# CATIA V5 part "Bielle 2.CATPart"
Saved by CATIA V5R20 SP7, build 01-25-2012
Part number: Bielle 2
Bounding box of the stored display mesh (mm): x -220 to 220, y 38.501 to 109.817, z 32.185 to 88.096
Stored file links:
  F:\Travaux\Modélisations\CFAO_2011\MMS\MMS_GR2\AA_OK\tquattrone\Catia\Bielle 2.CATPart
  C:\Users\Tom\Documents\Cours 2A\CFAO\Projet thinkmotion\Aileron_citroen.CATProduct
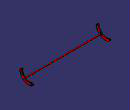
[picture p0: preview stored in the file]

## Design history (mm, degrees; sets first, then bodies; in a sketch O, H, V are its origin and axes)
Parameters
  Diametre_trou_bielle2 = 6 mm
  Epaisseur_bielle_2 = 5 mm
  `Distance_point/bielle2` = 5 mm
Set1
  Plane1 "Plan_bielle2/3": linked copy from another document
  Point1 "Point_bielle_21": linked copy from another document
  Point2 "Point_bielle_22": linked copy from another document
  Plane2 "Plan_sym": linked copy from another document
  Point3 "Point_bielle_11": linked copy from another document
  Plane3 "Plan_bielle1": linked copy from another document
Body1 (main body)
  Sketch1 on Plane1, origin (210, 0, 0), H (0, 1, 0), V (0, 0, 1)
    spline S1 through (49.3154, 81.8022) (52.0902, 68.1218) (61.1552, 54.5165) (77.3137, 44.9627) (95.4529, 44.3107) (100.0076, 45.2495) (108.0919, 44.8193) (109.4078, 38.541) (106.1441, 35.3786) (97.1685, 32.9047) (75.6566, 33.3551) (62.5105, 38.8193) (49.5126, 50.4629) (42.2393, 62.9606) (38.5014, 80.2129) (41.631, 87.7151) (44.3598, 88.0962) (46.5908, 87.3936)
    reference projected point E1 (44, 83) from Point2
    reference projected point E2 (104, 41) from Point1
    distance E1 S1 = 5 {= `Distance_point/bielle2`}
    distance E2 S1 = 5 {= `Distance_point/bielle2`}
  Pad1: profile Sketch1, direction (1, 0, 0), length 5 {= Epaisseur_bielle_2}
  Sketch2 on start face of Pad1, origin (210, 0, 0), H (0, -1, 0), V (0, 0, 1)
    circle A1 centre (-59.9679, 47.8572) radius 3
    radius A1 = 3 {= Diametre_trou_bielle2 /2}
  Pad2: profile Sketch2, direction (-1, 0, 0), up to Plane2
  Sketch3 on end face of Pad1, origin (215, 0, 0), H (0, 1, 0), V (0, 0, 1)
    circle A1 centre (104, 41) radius 3
    point P1 (104, 41)
    reference projected point E1 (104, 41) from Point3
    radius A1 = 3 {= Diametre_trou_bielle2 /2}
    coincidence: P1 E1
  Pad3: profile Sketch3, direction (1, 0, 0), up to Plane3
  Sketch4 on start face of Pad1, origin (210, 0, 0), H (0, -1, 0), V (0, 0, 1)
    circle A1 centre (-44, 83) radius 3
    point P1 (-44, 83)
    reference projected point E1 (-44, 83) from Point2
    radius A1 = 3 {= Diametre_trou_bielle2 /2}
    coincidence: P1 E1
  Pad4: profile Sketch4, direction (-1, 0, 0), length 5
  Mirror1: of the body so far, about Plane2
